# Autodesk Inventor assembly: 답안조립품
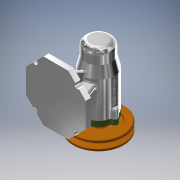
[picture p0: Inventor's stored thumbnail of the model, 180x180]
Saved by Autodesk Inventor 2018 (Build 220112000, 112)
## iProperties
Created: 2019-12
Part Number: 답안조립품
Document SubType Name: Assembly
Designer: Administrator
Author: Administrator
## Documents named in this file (12)
- C:\Users\Administrator\Desktop\491204v1069\답안조립품.iam
- C:\Users\Administrator\Desktop\491204v1069\본체.ipt
- C:\Users\Administrator\Desktop\491204v1069\볼트 M4.ipt
- C:\Users\Administrator\Desktop\491204v1069\멈춤나사 M3.ipt
- C:\Users\Administrator\Desktop\491204v1069\V벨트풀리.ipt
- C:\Users\Administrator\Desktop\491204v1069\베어링 6004.ipt
- C:\Users\Administrator\Desktop\491204v1069\베어링 51202.ipt
- C:\Users\Administrator\Desktop\491204v1069\어댑터슬리브.ipt
- C:\Users\Administrator\Desktop\491204v1069\오일 실.ipt
- C:\Users\Administrator\Desktop\491204v1069\축.ipt
- C:\Users\Administrator\Desktop\491204v1069\커버.ipt
- C:\Users\Administrator\Desktop\491204v1069\키 5 x 5 x 16.ipt
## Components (1 placed, 1 different names)
1. V벨트풀리:1
